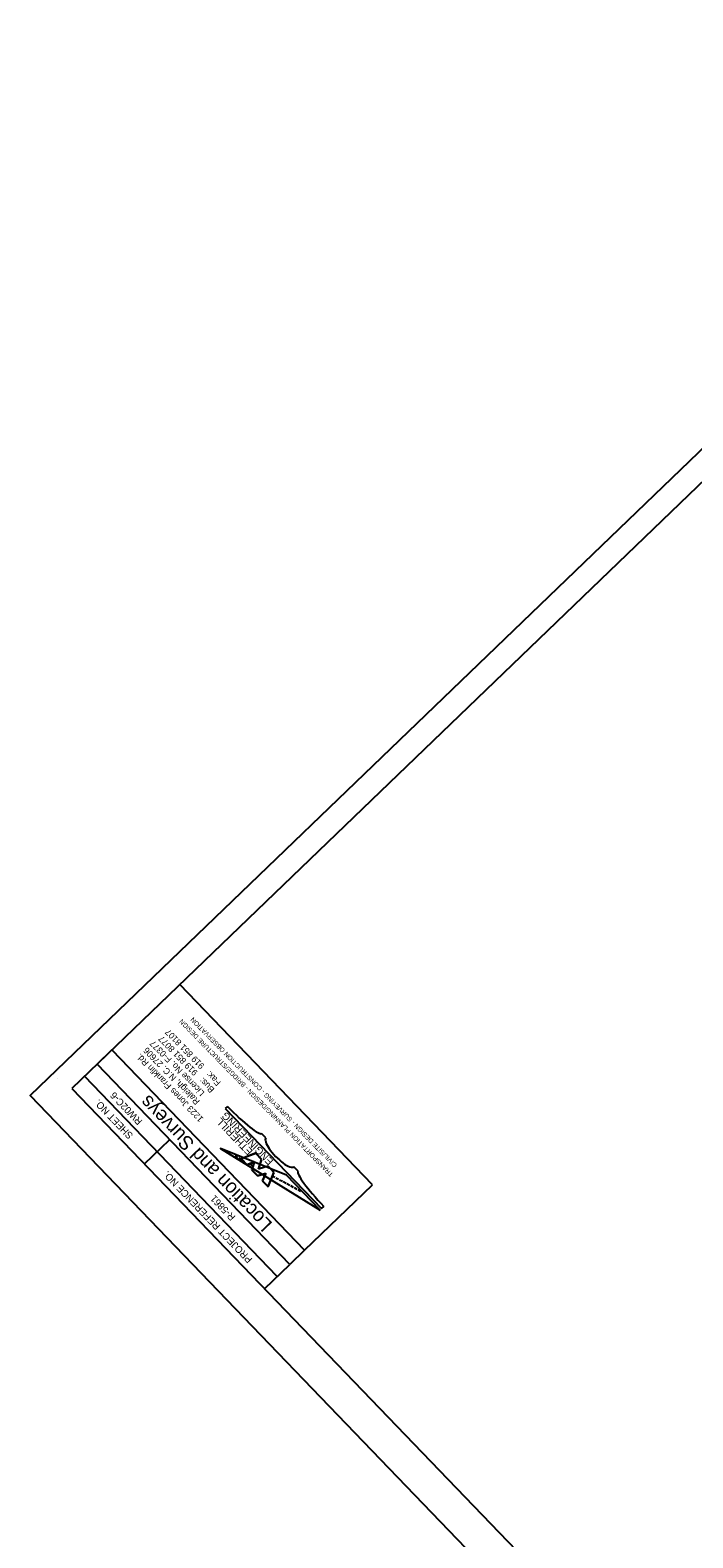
# Model space of a CAD drawing. Extents: x 473158 to 477500, y 500738 to 505114.
# Drawn here: x 473158 to 474209, y 502724 to 505114 of the extents above; entities that cross this region are included whole.
import ezdxf

# ---------------------------------------------------------------- set-up
doc = ezdxf.new("R2010")
doc.units = 0
for name, color, linetype in [('CTL Sheet Border CELL', 7, 'Continuous'), ('CTL Sheet Notes CELL', 7, 'Continuous'), ('Sheet Plot Border Outside CELL', 7, 'Continuous')]:
    doc.layers.add(name, color=color, linetype=linetype)

msp = doc.modelspace()

# ---------------------------------------------------------------- linework, layer by layer
at = {"layer": 'CTL Sheet Border CELL'}
for p, q in [((473700.8, 503283.5), (473395.3, 503600.9)), ((473200.9, 503452.3), (473200.9, 503452.3)), ((473200.9, 503452.3), (473200.9, 503452.3)), ((473549.7, 503138.1), (473244.2, 503455.6)), ((473158.2, 503425.1), (473158.2, 503425.1)), ((473339.4, 503316.7), (473379.3, 503355.1)), ((473593.1, 503179.9), (473700.7, 503283.5)), ((473529.7, 503118.9), (473569.6, 503157.3))]:
    msp.add_line(p, q, dxfattribs=at)
for points in [[(473224.2, 503436.3), (475527.6, 501042.6), (477203.2, 502655), (474899.8, 505048.7)], [(473569.6, 503157.3), (473264.2, 503474.8), (473287.6, 503497.4), (473593.1, 503179.9)]]:
    msp.add_lwpolyline(points, close=True, dxfattribs=at)
at = {"layer": 'CTL Sheet Notes CELL'}
for p, q in [((473471, 503407.8), (473467.4, 503404.3)), ((473467.4, 503404.3), (473620.1, 503246)), ((473532, 503357.8), (473525, 503365)), ((473487.4, 503326.4), (473482.9, 503328.8)), ((473493.2, 503323.3), (473488.8, 503325.6)), ((473492.4, 503324.7), (473501.5, 503315.2)), ((473515.8, 503333.3), (473493, 503324.6)), ((473493, 503324.6), (473501.6, 503315.6)), ((473501.5, 503315.2), (473513.5, 503319.7)), ((473501.6, 503315.6), (473514, 503320.3)), ((473510.9, 503313.9), (473506.5, 503316.2)), ((473513.5, 503319.7), (473509.3, 503307.1)), ((473514, 503320.3), (473509.7, 503307.2)), ((473525.1, 503323.7), (473515.8, 503333.3)), ((473525.4, 503323.8), (473515.9, 503333.7)), ((473520.1, 503308.4), (473525.1, 503323.7)), ((473520.6, 503308.9), (473525.4, 503323.8)), ((473509.3, 503307.1), (473518.3, 503297.8)), ((473509.7, 503307.2), (473518.4, 503298.2)), ((473518.3, 503297.8), (473531.1, 503301.5)), ((473518.4, 503298.2), (473531.7, 503302)), ((473535.5, 503312.9), (473520.1, 503308.4)), ((473535.6, 503313.2), (473520.6, 503308.9)), ((473531.1, 503301.5), (473526.1, 503289.7)), ((473531.7, 503302), (473526.5, 503289.8)), ((473535.2, 503280.8), (473544.7, 503303.3)), ((473535.3, 503280.2), (473545.1, 503303.3)), ((473544.7, 503303.3), (473535.5, 503312.9)), ((473545.1, 503303.3), (473535.6, 503313.2)), ((473546.2, 503295.1), (473541.8, 503297.5)), ((473552.1, 503292), (473547.7, 503294.3)), ((473582.8, 503305), (473575.9, 503312.2)), ((473526.1, 503289.7), (473535.3, 503280.2)), ((473526.5, 503289.8), (473535.2, 503280.8)), ((473558, 503288.8), (473553.6, 503291.2)), ((473563.9, 503285.7), (473559.5, 503288.1)), ((473569.8, 503282.6), (473565.3, 503284.9)), ((473575.6, 503279.4), (473571.2, 503281.8)), ((473581.5, 503276.3), (473577.1, 503278.7)), ((473587.4, 503273.2), (473583, 503275.5)), ((473620.1, 503246), (473623.7, 503249.4))]:
    msp.add_line(p, q, dxfattribs=at)
msp.add_lwpolyline([(473617.7, 503243.6), (473564.5, 503298.8), (473460.1, 503340.9)], close=True, dxfattribs=at)
msp.add_lwpolyline([(473515.9, 503333.7), (473515.5, 503333.5), (473492.4, 503324.7)], dxfattribs=at)
for centre, major_axis, ratio, start_param, end_param in [((473477.6, 503414.2), (-47.4, 49.2), 0.134146, 1.570796, 3.141593), ((473553.9, 503335), (-22, 22.8), 0.289474, 0, 3.141593), ((473630.3, 503255.8), (47.4, -49.2), 0.134146, 3.141593, 4.712389)]:
    msp.add_ellipse(centre, major_axis=major_axis, ratio=ratio, start_param=start_param, end_param=end_param, dxfattribs=at)
at = {"layer": 'Sheet Plot Border Outside CELL'}
msp.add_lwpolyline([(477499.6, 502426.8), (474913.6, 505114.2), (473158.2, 503425.1), (475744.2, 500737.7)], close=True, dxfattribs=at)

# ---------------------------------------------------------------- texts
at = {"layer": 'CTL Sheet Border CELL'}
for s, height, p in [('SHEET NO.', 11.07, (473322.2, 503362.6)), ('RW02C-6', 11.07, (473336.9, 503385)), ('Location and Surveys', 22.147, (473543.4, 503222.3)), ('PROJECT REFERENCE NO.', 11.074, (473511.2, 503165.9)), ('R-5861', 11.07, (473484.4, 503233.2))]:
    msp.add_text(s, height=height, rotation=133.8985, dxfattribs=at).set_placement(p)
at = {"layer": 'CTL Sheet Notes CELL'}
for s, height, rotation, p in [('TRANSPORTATION PLANNING/DESIGN - BRIDGE/STRUCTURE DESIGN', 7.333, 134.2745, (473639.3, 503300.5)), ('CIVIL/SITE DESIGN - SURVEYING - CONSTRUCTION OBSERVATION', 7.333, 134.2745, (473645.4, 503315.3)), ('License No. F-0377', 10, 134.2745, (473435.4, 503430)), ('Bus:   919 851 8077', 10, 134.2745, (473451.1, 503435.3)), ('Fax:   919 851 8107', 10, 134.2745, (473461.3, 503446.3)), ('1223 Jones Franklin Rd. ', 10, 134.2745, (473433.7, 503388.8)), ('Raleigh, N.C. 27606', 10, 134.2745, (473427.8, 503416.3)), ('ETHERILL', 11.67, 133.9481, (473511.9, 503337.3)), ('ENGINEERING', 11.667, 133.9481, (473544.7, 503321.7))]:
    msp.add_text(s, height=height, rotation=rotation, dxfattribs=at).set_placement(p)

doc.saveas('drawing.dxf')
